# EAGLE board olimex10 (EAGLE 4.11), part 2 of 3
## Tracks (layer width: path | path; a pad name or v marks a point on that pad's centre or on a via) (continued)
DIO00  (via drill 0.61)  (3 unrouted) (continued)
  Bottom 0.254: v52.07,121.92 25.4,121.92 IC13.12 | v68.58,27.94 67.31,29.21 42.55,29.21 41.27,27.94 RS08.36 39.37,27.94 39.37,24.77 38.73,24.13 25.4,24.13 24.13,22.86 IC34.8 18.41,22.86 v15.88,20.32 | IC43.17 277.5,22.23 299.08,22.23 304.8,27.94 304.8,60.33 279.4,60.33 278.13,59.05 278.13,57.15 280.04,57.15 281.31,58.42 RF08A.36 | IC48.1 55.88,163.83 60.96,158.75 130.81,158.75 131.44,159.38 143.51,159.38 144.78,158.12 222.25,158.12 223.52,159.38 227.33,159.38 229.24,157.48 248.92,157.48 250.19,158.75 251.46,157.48 251.46,154.94 245.75,154.94 244.47,153.67 SV3.2
DIO01  (via drill 0.61)  (3 unrouted)
  Top 0.254: v75.56,16.51 75.56,18.41 74.93,19.05 75.56,19.68 75.56,23.5 IC35.14 | v24.77,13.34 24.77,26.04 IC34.6 | IC13.11 29.21,123.19 29.21,125.73 27.3,127.64 7.62,127.64 7.62,26.04 12.06,21.59 17.14,21.59 17.14,12.7 15.24,10.79 SV1.4 | RF08A.37 284.48,44.45 280.67,40.64 280.67,24.13 282.57,22.23 282.57,3.17 276.23,3.17 274.32,5.08 IC43.15 | IC45.15 276.23,69.22 283.21,69.22 283.21,120.02 284.48,121.28 RF08B.37 | v122.56,164.47 130.18,156.84 143.51,156.84 143.51,177.16 151.13,184.78 v151.13,189.23 | v247.65,191.13 247.65,155.57 246.38,154.31 SV3.4
  Bottom 0.254: IC13.11 27.3,121.28 51.44,121.28 IC14.11 | IC34.6 24.13,27.94 25.4,26.67 36.2,26.67 37.47,25.4 RS08.37 | v75.56,16.51 72.39,13.34 41.27,13.34 40.64,12.7 24.77,12.7 | 24.77,12.7 19.68,12.7 19.05,13.34 17.78,13.34 15.24,10.79 SV1.4 | 24.77,12.7 v24.77,13.34 | v122.56,164.47 121.92,163.83 111.12,163.83 107.95,167 69.85,167 69.85,163.83 69.22,163.19 62.87,163.19 IC48.3 | v151.13,189.23 151.76,189.87 191.13,189.87 191.77,189.23 194.31,191.77 211.46,191.77 212.09,191.13 v247.65,191.13
DIO02  (via drill 0.61)  (3 unrouted)
  Top 0.254: v76.83,30.48 v76.83,41.91 76.2,42.55 76.2,73.66 74.93,74.93 74.93,81.28 v71.75,84.45 | v36.2,41.91 35.56,41.27 v35.56,29.21 | v26.04,29.21 26.04,29.84 IC34.4 | SV1.6 v17.78,30.48 | v59.05,84.45 59.69,85.09 59.69,114.3 55.88,118.11 IC14.10 | RF08A.35 281.94,57.15 285.12,57.15 285.75,56.52 285.75,55.24 285.12,54.61 285.12,43.81 283.21,41.91 283.21,2.54 274.32,2.54 271.78,5.08 IC43.14 | v280.04,84.45 280.04,107.31 281.94,109.22 RF08B.35 | v248.92,161.29 SV3.6
  Bottom 0.254: IC13.10 31.11,116.2 46.35,116.2 46.99,116.84 54.61,116.84 55.88,118.11 IC14.10 | v36.2,41.91 v76.83,41.91 | v76.83,30.48 IC35.16 | RS08.35 36.83,27.94 v35.56,29.21 v26.04,29.21 | v17.78,30.48 20.32,33.02 IC34.4 | v71.75,84.45 v59.05,84.45 | v280.04,84.45 271.78,84.45 IC45.14 | v248.92,161.29 227.97,161.29 227.33,160.66 226.06,160.66 225.43,161.29 212.72,161.29 210.19,158.75 159.38,158.75 156.84,161.29 144.15,161.29 143.51,160.66 132.08,160.66 131.44,161.29 106.05,161.29 105.41,160.66 104.78,161.29 59.69,161.29 59.69,166.37 60.33,167 64.14,167 IC48.5
DIO03  (via drill 0.61)  (3 unrouted)
  Top 0.254: 25.4,35.56 26.04,34.92 v26.04,33.02 | IC34.2 25.4,35.56 | v68.58,31.75 72.39,35.56 IC35.18 | v19.68,38.1 20.32,37.47 SV1.8 | 25.4,35.56 25.4,64.77 26.67,66.04 26.67,114.3 30.48,118.11 IC13.9 | RF08A.33 279.4,55.24 281.31,53.34 281.31,42.55 280.04,41.27 280.04,18.41 281.31,17.14 281.31,12.06 279.4,10.16 279.4,4.45 276.23,4.45 275.59,5.08 275.59,7.62 274.95,8.26 271.14,8.26 IC43.13 | IC45.13 271.78,68.58 298.45,68.58 298.45,114.94 287.02,126.36 278.13,126.36 278.13,123.83 279.4,122.56 RF08B.33 | v250.19,157.48 251.46,156.21 SV3.8 | v131.44,158.12 IC50.1
  Bottom 0.254: IC13.9 33.02,116.84 45.72,116.84 46.35,117.47 53.98,117.47 54.61,118.11 54.61,121.28 56.52,121.28 IC14.9 | v26.04,33.02 27.3,31.75 33.02,31.75 34.29,30.48 RS08.33 38.73,30.48 40.01,31.75 v68.58,31.75 | v19.68,38.1 IC34.2 | v131.44,158.12 132.72,156.84 249.56,156.84 v250.19,157.48
DIO04  (via drill 0.61)  (3 unrouted)
  Top 0.254: SV1.10 22.86,9.53 24.13,8.26 24.13,6.99 25.4,5.71 39.37,5.71 39.37,19.68 41.91,22.23 v41.91,36.83 41.91,41.27 40.64,42.55 RS08.24 | v70.48,68.58 69.85,69.22 69.85,105.41 IC15.2 | v52.7,36.83 53.34,37.47 53.34,62.23 54.61,63.5 v54.61,67.31 | RF08A.24 266.06,58.42 265.43,57.78 265.43,53.98 266.7,52.7 IC42.21 | IC39.21 266.7,113.03 265.43,114.3 265.43,122.56 266.7,123.83 RF08B.24 | v219.71,171.45 219.71,174.62 212.09,182.25 212.09,196.22 170.18,196.22 165.74,191.77 147.32,191.77 138.43,182.88 138.43,179.71 133.99,179.71 133.35,180.34 133.35,183.51 128.91,183.51 128.27,182.88 128.27,167.64 129.54,166.37 IC50.3 | v253.37,172.72 254,172.09 SV3.10
  Bottom 0.254: IC26.17 31.75,66.04 32.38,66.67 33.66,66.67 34.29,67.31 v54.61,67.31 63.5,67.31 64.77,68.58 IC28.3 v70.48,68.58 | v41.91,36.83 v52.7,36.83 | v219.71,171.45 219.71,173.99 252.09,173.99 v253.37,172.72
DIO05  (via drill 0.61)  (3 unrouted)
  Top 0.254: v44.45,11.43 v44.45,40.64 v44.45,62.23 | v69.22,63.5 69.22,106.05 73.66,110.49 IC15.1 | RF08A.26 268.61,58.42 267.97,57.78 267.97,53.98 269.24,52.7 IC42.20 | IC39.20 269.24,113.03 267.97,114.3 267.97,122.56 269.24,123.83 RF08B.26 | v187.32,167 188.59,168.91 v188.59,170.81 | v250.19,168.28 250.19,173.35 250.82,173.99 254.63,173.99 254.63,156.21 256.54,154.31 SV3.12
  Bottom 0.254: v44.45,11.43 27.3,11.43 26.04,10.16 SV1.12 | v44.45,40.64 RS08.26 | IC26.15 31.75,60.96 33.02,62.23 v44.45,62.23 63.5,62.23 64.77,63.5 IC28.5 v69.22,63.5 | v187.32,167 136.53,167 IC50.5 | v188.59,170.81 189.23,170.18 205.1,170.18 205.74,170.81 210.82,170.81 213.36,168.28 214,168.28 214.63,167.64 249.56,167.64 v250.19,168.28
DIO06  (via drill 0.61)  (3 unrouted)
  Top 0.254: RS08.28 40.64,38.73 39.37,40.01 39.37,46.35 38.73,46.99 37.47,46.99 35.56,48.9 35.56,54.61 v34.29,55.88 34.29,57.78 v36.2,59.69 | v62.87,59.69 62.87,73.03 65.41,75.56 65.41,126.36 69.22,126.36 69.85,125.73 69.85,123.19 72.39,120.65 72.39,117.47 74.3,117.47 IC15.13 | v28.57,39.37 28.57,11.43 27.94,10.79 SV1.14 | RF08A.28 271.14,58.42 270.51,57.78 270.51,53.98 271.78,52.7 IC42.19 | IC39.19 271.78,113.03 270.51,114.3 270.51,122.56 271.78,123.83 RF08B.28 | v196.85,160.02 193.04,163.83 IC52.1 | v208.28,160.66 208.91,161.29 208.91,163.19 209.55,163.83 209.55,170.18 213.36,173.99 v213.36,179.71 | v253.37,179.71 257.18,175.9 257.18,161.93 258.44,160.66 258.44,153.67 SV3.14
  Bottom 0.254: v34.29,55.88 IC26.13 | v36.2,59.69 v62.87,59.69 63.5,59.69 64.77,58.42 IC28.7 | v28.57,39.37 38.73,39.37 40.01,38.1 RS08.28 | v196.85,160.02 197.49,159.38 207.01,159.38 v208.28,160.66 | v213.36,179.71 214,179.07 252.73,179.07 v253.37,179.71
DIO07  (via drill 0.61)  (3 unrouted)
  Top 0.254: v77.47,54.61 76.83,55.24 76.83,63.5 77.47,64.14 77.47,116.84 78.74,118.11 IC15.12 | SV1.16 30.48,10.79 31.75,12.06 31.75,16.51 32.38,17.14 32.38,41.27 31.11,42.55 31.11,50.16 IC26.11 | v45.72,52.07 v45.72,35.56 | RF08A.30 273.69,58.42 273.05,57.78 273.05,53.98 274.32,52.7 IC42.18 | IC39.18 274.32,113.03 273.05,114.3 273.05,122.56 274.32,123.83 RF08B.30 | v235.59,147.96 235.59,160.02 234.31,160.02 233.04,158.75 233.04,156.84 201.29,156.84 199.39,158.75 199.39,162.56 198.12,163.83 IC52.3
  Bottom 0.254: IC26.11 31.75,50.8 33.02,52.07 v45.72,52.07 57.78,52.07 59.05,53.34 IC28.9 68.58,53.34 69.85,54.61 v77.47,54.61 | v45.72,35.56 RS08.30 | v235.59,147.96 265.43,147.96 267.97,150.5 267.97,152.4 263.52,152.4 262.25,153.67 SV3.16
DIO08  (via drill 0.61)  (3 unrouted)
  Top 0.254: v43.18,54.61 v43.18,49.53 v43.18,33.02 43.18,22.23 41.91,20.95 41.91,15.24 v40.64,13.97 | v69.22,117.47 68.58,116.84 68.58,64.14 67.94,63.5 67.94,60.96 70.48,58.42 v70.48,52.07 | SV1.18 v33.02,13.97 | RF08A.32 276.23,58.42 275.59,57.78 275.59,53.98 276.86,52.7 IC42.17 | IC39.17 276.86,113.03 275.59,114.3 275.59,122.56 276.86,123.83 RF08B.32 | v212.09,163.83 214.63,166.37 v214.63,168.91 | v262.89,170.81 262.89,155.57 264.16,154.31 SV3.18
  Bottom 0.254: v43.18,54.61 29.21,54.61 27.94,55.88 IC26.8 | v43.18,33.02 RS08.32 | v43.18,49.53 48.26,49.53 48.9,48.9 49.53,48.9 50.8,50.16 57.15,50.16 59.05,52.07 v70.48,52.07 71.12,52.07 72.39,53.34 IC28.12 | v69.22,117.47 69.85,116.84 78.74,116.84 IC15.11 | v33.02,13.97 v40.64,13.97 | v212.09,163.83 210.19,163.83 209.55,163.19 203.2,163.19 IC52.5 | v214.63,168.91 215.26,168.28 248.92,168.28 251.46,170.81 v262.89,170.81
DIO09  (via drill 0.61)  (3 unrouted)
  Top 0.254: v27.3,33.02 27.3,29.21 26.67,28.57 26.67,6.35 36.2,6.35 36.83,6.99 36.83,8.26 35.56,9.53 SV1.20 | v78.11,59.69 78.11,62.23 82.55,66.67 82.55,116.84 83.82,118.11 IC15.10 | v18.41,36.83 17.14,38.1 v17.14,59.05 | RF08A.29 274.95,55.88 274.95,47.62 275.59,46.99 275.59,43.81 274.32,42.55 IC42.15 | IC39.15 274.32,97.79 275.59,99.06 275.59,113.03 274.32,114.3 RF08B.29 | v261.62,158.12 IC54.1
  Bottom 0.254: v27.3,33.02 28.57,34.29 32.38,34.29 | 32.38,34.29 35.56,34.29 36.83,35.56 RS08.29 | v78.11,59.69 76.83,58.42 IC28.14 71.12,58.42 69.85,57.15 37.47,57.15 34.92,59.69 29.21,59.69 28.57,60.33 24.77,60.33 24.13,60.96 IC26.6 19.05,60.96 v17.14,59.05 | 32.38,34.29 32.38,36.83 v18.41,36.83 | v261.62,158.12 266.06,153.67 SV3.20
DIO10  (via drill 0.61)  (3 unrouted)
  Top 0.254: v19.68,66.04 20.32,65.41 20.32,46.35 v19.68,45.72 | v35.56,45.72 36.83,44.45 36.83,42.55 37.47,41.91 36.83,41.27 36.83,40.01 | 36.83,40.01 38.1,38.73 RS08.27 | v67.31,45.09 71.75,49.53 71.75,61.59 IC28.16 | v85.09,84.45 85.09,116.84 86.36,118.11 IC15.9 | v80.64,83.19 78.11,80.64 v78.11,63.5 | 36.83,40.01 36.83,22.23 37.47,21.59 37.47,11.43 38.1,10.79 SV1.22 | RF08A.27 272.42,55.88 272.42,47.62 273.05,46.99 273.05,43.81 271.78,42.55 IC42.14 | IC39.14 271.78,97.79 273.05,99.06 273.05,113.03 271.78,114.3 RF08B.27 | v266.7,156.84 IC54.3
  Bottom 0.254: v19.68,45.72 v35.56,45.72 36.83,44.45 41.27,44.45 41.91,43.81 66.04,43.81 v67.31,45.09 | v19.68,66.04 IC26.4 | v85.09,84.45 83.82,83.19 v80.64,83.19 | IC28.16 v78.11,63.5 | v266.7,156.84 269.24,154.31 SV3.22
DIO11  (via drill 0.61)  (3 unrouted)
  Top 0.254: 33.02,64.77 33.02,52.07 34.29,50.8 v34.29,42.55 | 33.02,64.77 v33.02,67.94 | v70.48,66.04 70.48,66.67 72.39,68.58 IC28.18 70.48,71.75 70.48,89.53 72.39,91.44 v72.39,99.06 | 33.02,64.77 v33.66,64.77 | v90.17,99.69 90.17,116.84 88.9,118.11 IC15.8 | v46.99,38.1 46.99,6.35 42.55,6.35 41.91,6.99 41.91,8.26 40.64,9.53 SV1.24 | RF08A.25 269.88,55.88 269.88,47.62 270.51,46.99 270.51,43.81 269.24,42.55 IC42.13 | IC39.13 269.24,97.79 270.51,99.06 270.51,113.03 269.24,114.3 RF08B.25 | SV3.24 IC54.5
  Bottom 0.254: v33.02,67.94 32.38,67.31 27.94,67.31 24.13,71.12 IC26.2 | v34.29,42.55 36.2,40.64 RS08.25 38.73,40.64 40.01,39.37 45.72,39.37 v46.99,38.1 | v70.48,66.04 69.22,64.77 v33.66,64.77 | v90.17,99.69 89.53,99.06 v72.39,99.06
DIOEVEN  (via drill 0.61)  (2 unrouted)
  Top 0.254: v45.72,30.48 v45.72,26.67 | v60.33,114.94 62.23,113.03 62.23,92.08 60.33,90.17 60.33,40.64 61.59,39.37 61.59,23.5 64.77,20.32 IC35.9 | v287.02,88.9 285.75,90.17 285.75,125.09 285.12,125.73 279.4,125.73 RF08B.34
  Bottom 0.254: v45.72,26.67 59.69,26.67 IC35.9 | RS08.34 v45.72,30.48 | v60.33,114.94 59.69,114.3 46.99,114.3 46.35,114.94 24.77,114.94 IC13.13 | IC43.18 276.23,23.5 286.38,23.5 287.02,22.86 298.45,22.86 304.17,28.57 304.17,59.69 281.31,59.69 280.04,58.42 RF08A.34 | v287.02,88.9 276.86,88.9 IC45.18
DMA00  (via drill 0.61)  (3 unrouted)
  Top 0.254: v137.16,11.43 135.89,10.16 DMA0-3.7 128.91,4.45 v128.91,3.17 | 46.99,54.61 v45.72,53.34 | 46.99,54.61 v46.99,86.36 | SV2.1 v43.18,90.17 | v73.66,6.99 60.33,20.32 v60.33,39.37 | v47.62,39.37 46.99,40.01 46.99,54.61 | IC43.25 256.54,27.3 255.27,28.57 255.27,31.75 256.54,33.02 IC42.25 256.54,52.7 255.27,53.98 255.27,57.78 255.91,58.42 RF08A.16 | IC45.25 256.54,87.63 255.27,88.9 255.27,107.95 256.54,109.22 IC39.25 256.54,113.03 255.27,114.3 255.27,122.56 256.54,123.83 RF08B.16 | v121.28,189.87 121.28,191.13 71.75,191.13 IC47.9 | v191.77,190.5 v194.31,190.5 | v270.51,191.13 270.51,182.88 271.78,181.61 IC53.5 | v285.75,163.83 285.75,188.59 287.02,189.87 SV4.24
  Bottom 0.254: v137.16,11.43 162.56,11.43 163.83,12.7 IC38.8 | v45.72,53.34 RS08.16 | v46.99,86.36 SV2.1 | v43.18,90.17 35.56,90.17 33.66,88.27 19.05,88.27 19.05,85.72 18.41,85.09 17.14,85.09 15.88,83.82 SV2.24 | v128.91,3.17 128.27,2.54 96.52,2.54 93.98,5.08 78.11,5.08 77.47,4.45 76.2,4.45 v73.66,6.99 | v60.33,39.37 v47.62,39.37 | v121.28,189.87 123.83,187.32 135.25,187.32 135.89,187.96 135.89,191.13 166.37,191.13 167,190.5 v191.77,190.5 | v194.31,190.5 194.94,189.87 196.22,189.87 196.85,189.23 197.49,189.87 243.84,189.87 244.47,189.23 260.35,189.23 261.62,190.5 270.51,190.5 | 270.51,190.5 SV4.24 | 270.51,190.5 v270.51,191.13 | v285.75,163.83 287.65,163.83 288.93,162.56 SV4.1
DMA01  (via drill 0.61)  (3 unrouted)
  Top 0.254: 40.64,80.64 39.37,79.38 39.37,50.16 40.64,48.9 RS08.20 | 40.64,80.64 40.64,81.92 39.37,83.19 39.37,84.45 40.64,85.72 SV2.3 | v92.71,11.43 90.17,13.97 v90.17,44.45 | v57.78,79.38 v57.78,45.72 | 40.64,80.64 v41.91,79.38 | IC43.23 261.62,27.3 260.35,28.57 260.35,31.75 261.62,33.02 IC42.23 261.62,52.7 260.35,53.98 260.35,57.78 260.99,58.42 RF08A.20 | IC45.23 261.62,87.63 260.99,88.27 260.99,94.61 260.35,95.25 260.35,106.05 261.62,107.31 IC39.23 261.62,113.03 260.35,114.3 260.35,122.56 261.62,123.83 RF08B.20 | v80.01,186.06 65.41,186.06 IC47.11 | v138.43,184.15 146.05,191.77 146.05,193.68 149.22,196.85 280.67,196.85 280.67,173.99 281.94,172.72 280.67,171.45 280.67,166.37 285.75,161.29 288.29,161.29 288.29,163.19 289.56,164.47 SV4.3
  Bottom 0.254: IC38.6 163.83,17.78 162.56,16.51 139.7,16.51 135.89,12.7 DMA0-3.6 110.49,12.7 109.22,11.43 v92.71,11.43 | v90.17,44.45 69.22,44.45 67.31,46.35 58.42,46.35 v57.78,45.72 | v41.91,79.38 v57.78,79.38 | v80.01,186.06 87.63,178.44 136.53,178.44 138.43,180.34 v138.43,184.15
DMA02  (via drill 0.61)  (3 unrouted)
  Top 0.254: v49.53,55.88 v49.53,88.9 | v40.64,91.44 38.1,88.9 SV2.5 | v132.72,19.05 132.72,20.95 DMA0-3.2 | v84.45,20.32 80.64,24.13 v80.64,57.15 | IC43.26 254,27.3 252.73,28.57 252.73,31.75 254,33.02 IC42.26 254,52.7 252.73,53.98 252.73,57.78 253.37,58.42 RF08A.14 | IC45.26 254,87.63 252.73,88.9 252.73,109.22 254,110.49 IC39.26 254,113.03 252.73,114.3 252.73,122.56 254,123.83 RF08B.14 | v120.02,165.1 120.02,157.48 79.38,157.48 77.47,159.38 77.47,161.29 40.01,161.29 29.21,172.09 29.21,175.9 43.18,189.87 43.18,191.13 57.78,191.13 57.78,189.87 58.42,189.23 IC47.13
  Bottom 0.254: DMA0-3.2 135.89,22.86 137.16,21.59 162.56,21.59 163.83,22.86 IC38.4 | v49.53,88.9 46.99,91.44 v40.64,91.44 | RS08.14 v49.53,55.88 50.8,54.61 68.58,54.61 71.12,57.15 v80.64,57.15 | v132.72,19.05 132.08,18.41 94.61,18.41 92.71,20.32 v84.45,20.32 | v120.02,165.1 121.92,167 135.25,167 136.53,168.28 204.47,168.28 205.1,167.64 213.36,167.64 214,167 252.09,167 252.73,167.64 283.85,167.64 285.12,166.37 287.65,166.37 288.93,167.64 SV4.5
DMA03  (via drill 0.61)  (3 unrouted)
  Top 0.254: v139.06,29.21 139.06,24.77 DMA0-3.3 | v159.38,30.48 v161.93,27.94 | v48.26,85.09 v48.26,58.42 v48.26,48.26 | v93.34,21.59 90.81,24.13 90.81,43.81 91.44,44.45 91.44,45.72 v90.17,46.99 | IC43.27 251.46,27.3 250.19,28.57 250.19,31.75 251.46,33.02 IC42.27 251.46,52.7 250.19,53.98 250.19,57.78 250.82,58.42 RF08A.12 | IC45.27 251.46,87.63 250.82,88.27 250.82,94.61 250.19,95.25 250.19,98.42 251.46,99.69 IC39.27 251.46,113.03 250.19,114.3 250.19,122.56 251.46,123.83 RF08B.12 | v183.51,186.06 189.23,180.34 189.23,173.35 193.68,168.91 193.68,167 194.31,166.37 194.31,163.83 194.94,163.19 196.85,163.19 196.85,168.91 199.39,171.45 199.39,173.99 201.93,176.53 201.93,184.15 204.47,186.69 204.47,189.23 205.1,189.87 209.55,189.87 v209.55,175.26
  Bottom 0.254: v139.06,29.21 140.34,30.48 v159.38,30.48 | v161.93,27.94 IC38.2 | v48.26,85.09 37.47,85.09 36.2,86.36 SV2.7 | v48.26,58.42 RS08.12 | v93.34,21.59 95.89,19.05 125.09,19.05 126.36,20.32 DMA0-3.3 | v90.17,46.99 87.63,49.53 80.01,49.53 78.11,47.62 52.7,47.62 52.07,48.26 v48.26,48.26 | v183.51,186.06 140.34,186.06 IC49.9 | v209.55,175.26 210.19,175.9 280.67,175.9 281.31,175.26 285.12,175.26 286.38,176.53 287.65,176.53 288.29,175.9 288.29,170.81 289.56,170.81 SV4.7
DMA04  (via drill 0.61)  (3 unrouted)
  Top 0.254: v35.56,60.96 35.56,78.11 34.29,79.38 v34.29,82.55 | v124.46,80.01 124.46,73.03 125.73,71.75 v125.73,64.77 | v138.43,61.59 137.79,60.96 137.79,50.16 135.89,48.26 132.72,48.26 132.72,46.35 DMA4-7.7 | IC43.5 248.92,18.41 250.19,19.68 250.19,22.86 249.56,23.5 249.56,29.84 IC42.5 249.56,31.11 249.56,32.38 250.19,33.02 250.19,46.99 249.56,47.62 249.56,55.88 RF08A.9 | IC45.5 248.92,72.39 250.19,73.66 250.19,93.98 248.92,95.25 IC39.5 248.92,98.42 250.19,99.69 250.19,113.03 249.56,113.67 249.56,120.65 248.92,121.28 RF08B.9 | IC49.11 v139.06,196.22
  Bottom 0.254: v35.56,60.96 RS08.9 | SV2.9 33.02,85.72 34.29,85.72 v34.29,82.55 38.73,78.11 60.96,78.11 64.14,81.28 93.98,81.28 95.89,83.19 97.16,83.19 97.79,82.55 97.79,79.38 120.65,79.38 121.28,80.01 v124.46,80.01 | DMA4-7.7 135.89,44.45 139.7,48.26 153.03,48.26 155.57,45.72 160.66,45.72 161.93,46.99 IC31.8 | v125.73,64.77 135.25,64.77 v138.43,61.59 | v139.06,196.22 139.7,196.85 290.19,196.85 292.74,194.31 292.74,173.35 289.56,173.35 SV4.9
DMA05  (via drill 0.61)  (3 unrouted)
  Top 0.254: v35.56,79.38 v36.83,78.11 36.83,73.03 36.2,72.39 36.2,61.59 36.83,60.96 36.83,60.33 38.1,59.05 RS08.11 | v138.43,41.91 138.43,43.18 DMA4-7.6 | v158.12,40.01 160.02,41.91 160.02,50.8 v161.29,52.07 | v62.23,78.11 61.59,77.47 61.59,44.45 63.5,42.55 v63.5,40.64 | IC43.6 251.46,18.41 252.73,19.68 252.73,22.86 252.09,23.5 252.09,29.84 IC42.6 252.09,31.11 252.09,32.38 252.73,33.02 252.73,46.99 252.09,47.62 252.09,55.88 RF08A.11 | IC45.6 251.46,72.39 252.73,73.66 252.73,87.63 251.46,88.9 IC39.6 252.09,97.16 252.09,109.86 252.73,110.49 252.73,113.03 252.09,113.67 252.09,120.65 251.46,121.28 RF08B.11 | v128.27,194.31 128.27,191.77 127,190.5 IC49.13
  Bottom 0.254: v35.56,79.38 31.75,83.19 31.75,84.45 30.48,85.72 SV2.11 | v138.43,41.91 140.34,40.01 v158.12,40.01 | v161.29,52.07 IC31.6 | v36.83,78.11 37.47,77.47 61.59,77.47 v62.23,78.11 | v63.5,40.64 64.77,39.37 118.75,39.37 123.83,44.45 130.81,44.45 133.35,46.99 DMA4-7.6 | v128.27,194.31 128.91,194.94 171.45,194.94 172.72,196.22 289.56,196.22 292.1,193.68 292.1,175.9 289.56,175.9 SV4.11
DMA06  (via drill 0.61)  (3 unrouted)
  Top 0.254: v19.05,55.88 18.41,56.52 18.41,59.05 16.51,60.96 v16.51,75.56 16.51,80.64 13.97,83.19 13.97,91.44 v14.61,92.08 | v117.47,59.69 116.2,60.96 v116.2,77.47 | v90.81,78.11 91.44,78.74 91.44,93.98 90.17,95.25 90.17,98.42 88.9,99.69 v88.9,100.97 | IC43.7 254,18.41 255.27,19.68 255.27,22.86 254.63,23.5 254.63,29.84 IC42.7 254.63,31.11 254.63,32.38 255.27,33.02 255.27,46.99 254.63,47.62 254.63,55.88 RF08A.13 | IC45.7 254,72.39 255.27,73.66 255.27,87.63 254,88.9 IC39.7 254,107.95 255.27,109.22 255.27,113.03 254.63,113.67 254.63,120.65 254,121.28 RF08B.13 | v207.01,177.16 207.01,185.42 205.74,186.69 IC51.9
  Bottom 0.254: IC31.4 163.83,57.15 162.56,55.88 137.16,55.88 135.89,57.15 DMA4-7.2 133.35,57.15 132.72,57.78 129.54,57.78 127.64,59.69 v117.47,59.69 | v19.05,55.88 20.32,55.88 21.59,57.15 36.2,57.15 37.47,55.88 RS08.13 | v16.51,75.56 24.13,83.19 24.13,85.09 26.04,85.09 27.3,86.36 SV2.13 | v116.2,77.47 115.57,78.11 v90.81,78.11 | v88.9,100.97 88.27,100.33 73.66,100.33 73.03,100.97 61.59,100.97 60.96,101.6 45.09,101.6 41.91,98.42 12.06,98.42 11.43,97.79 11.43,95.89 10.79,95.89 8.26,93.34 8.26,88.27 10.79,88.27 v14.61,92.08 | v207.01,177.16 207.65,177.8 281.31,177.8 282.57,179.07 287.65,179.07 288.93,177.8 SV4.13
DMA07  (via drill 0.61)  (3 unrouted)
  Top 0.254: v137.16,64.14 137.16,57.15 DMA4-7.3 | v36.83,49.53 36.83,51.44 38.1,52.7 RS08.15 | v113.67,45.72 117.47,49.53 v117.47,57.15 | v52.07,46.99 v52.07,92.71 | v25.4,89.53 SV2.15 | IC43.8 256.54,18.41 257.81,19.68 257.81,22.86 257.18,23.5 257.18,29.84 IC42.8 257.18,31.11 257.18,32.38 257.81,33.02 257.81,46.99 257.18,47.62 257.18,55.88 RF08A.15 | IC45.8 256.54,72.39 257.81,73.66 257.81,87.63 256.54,88.9 IC39.8 256.54,98.42 257.81,99.69 257.81,113.03 257.18,113.67 257.18,120.65 256.54,121.28 RF08B.15 | IC51.11 v207.65,194.94
  Bottom 0.254: v137.16,64.14 138.43,65.41 163.19,65.41 163.83,66.04 173.99,66.04 174.62,65.41 174.62,63.5 167.64,63.5 166.37,62.23 IC31.2 | v36.83,49.53 41.91,49.53 44.45,46.99 v52.07,46.99 88.9,46.99 90.17,45.72 v113.67,45.72 | v117.47,57.15 130.81,57.15 133.35,54.61 DMA4-7.3 | v25.4,89.53 28.57,92.71 v52.07,92.71 | v207.65,194.94 208.28,195.58 288.93,195.58 291.46,193.04 291.46,180.97 289.56,180.97 SV4.15
DMA08  (via drill 0.61)  (3 unrouted)
  Top 0.254: v137.79,83.82 137.79,81.92 DMA8-11.7 | v159.38,85.09 160.66,83.82 v160.66,81.28 | v33.02,50.8 32.38,50.16 v32.38,42.55 | v10.16,41.91 8.89,43.18 v8.89,81.28 | v130.81,80.64 130.18,81.28 v130.18,93.98 | v99.06,93.98 97.79,95.25 v97.79,99.06 | IC43.9 259.08,18.41 260.35,19.68 260.35,22.86 259.71,23.5 259.71,29.84 IC42.9 259.71,31.11 259.71,32.38 260.35,33.02 260.35,46.99 259.71,47.62 259.71,55.88 RF08A.17 | IC45.9 259.08,72.39 260.35,73.66 260.35,93.98 259.08,95.25 IC39.9 259.08,106.05 260.35,107.31 260.35,113.03 259.71,113.67 259.71,120.65 259.08,121.28 RF08B.17 | IC51.13 v195.58,194.31 | v288.29,191.77 288.29,184.78 289.56,183.51 SV4.17
  Bottom 0.254: v137.79,83.82 139.06,85.09 v159.38,85.09 | v160.66,81.28 IC24.8 | v32.38,42.55 31.75,41.91 v10.16,41.91 | 9.53,81.92 10.16,82.55 20.95,82.55 21.59,83.19 21.59,86.36 SV2.17 | v8.89,81.28 9.53,81.92 | v33.02,50.8 RS08.17 | v130.81,80.64 131.44,80.64 133.35,78.74 DMA8-11.7 | v99.06,93.98 v130.18,93.98 | v97.79,99.06 94.61,102.23 88.9,102.23 87.63,100.97 74.3,100.97 73.66,101.6 62.23,101.6 61.59,102.23 44.45,102.23 41.27,99.06 9.53,99.06 5.08,94.61 5.08,81.92 9.53,81.92 | v195.58,194.31 196.22,193.68 210.82,193.68 212.09,194.94 283.21,194.94 286.38,191.77 v288.29,191.77
DMA09  (via drill 0.61)  (3 unrouted)
  Top 0.254: v136.53,85.09 136.53,83.19 DMA8-11.6 | v42.55,63.5 41.91,62.87 41.91,46.99 40.01,46.99 38.73,48.26 RS08.19 | v45.09,63.5 46.35,64.77 46.35,85.72 45.72,86.36 45.72,87 v46.35,87.63 | IC43.10 261.62,18.41 262.89,19.68 262.89,22.86 262.25,23.5 262.25,29.84 IC42.10 262.25,31.11 262.25,32.38 262.89,33.02 262.89,55.24 262.25,55.88 RF08A.19 | IC45.10 261.62,72.39 262.89,73.66 262.89,88.27 261.62,89.53 IC39.10 261.62,97.79 262.89,99.06 262.89,120.02 261.62,121.28 RF08B.19 | v278.13,184.15 IC53.9
  Bottom 0.254: IC24.6 162.56,86.36 161.29,87.63 139.06,87.63 v136.53,85.09 128.27,85.09 127,86.36 52.07,86.36 50.8,87.63 v46.35,87.63 20.95,87.63 20.32,87 SV2.19 | v42.55,63.5 v45.09,63.5 | v278.13,184.15 287.65,184.15 288.93,185.42 SV4.19
DMA10  (via drill 0.61)  (3 unrouted)
  Top 0.254: v6.35,46.99 v6.35,83.19 | v126.36,91.44 125.73,90.81 v125.73,84.45 | v50.8,81.92 v50.8,45.72 | 265.43,29.21 265.43,19.68 264.16,18.41 IC43.11 | 265.43,29.21 IC42.11 | 265.43,29.21 265.43,46.99 264.16,48.26 RF08A.21 | 265.43,93.98 265.43,73.66 264.16,72.39 IC45.11 | 265.43,93.98 264.16,95.25 IC39.11 | 265.43,93.98 265.43,113.03 264.8,113.67 264.8,120.65 264.16,121.28 RF08B.21
  Bottom 0.254: IC24.4 163.83,91.44 162.56,90.17 137.16,90.17 135.89,91.44 DMA8-11.2 v126.36,91.44 | 36.2,46.99 37.47,45.72 RS08.21 | 36.2,46.99 v6.35,46.99 | v6.35,83.19 8.26,85.09 15.88,85.09 17.14,86.36 SV2.21 | v125.73,84.45 100.97,84.45 100.33,83.82 99.06,83.82 97.16,85.72 54.61,85.72 v50.8,81.92 | v50.8,45.72 50.16,46.35 41.91,46.35 41.27,46.99 36.2,46.99 | IC53.11 271.14,186.06 281.31,186.06 281.94,186.69 287.65,186.69 288.93,187.96 SV4.21
DMA11  (via drill 0.61)  (3 unrouted)
  Top 0.254: v161.93,96.52 v161.93,99.06 | DMA8-11.3 137.16,91.44 v137.16,98.42 130.18,105.41 130.18,108.58 128.27,110.49 128.27,120.02 v125.09,123.19 | v27.94,44.45 27.3,45.09 27.3,50.16 27.94,50.8 v27.94,58.42 | v19.05,59.69 19.05,65.41 18.41,66.04 18.41,82.55 19.05,83.19 19.05,84.45 18.41,85.09 16.51,85.09 | 16.51,85.09 15.24,85.09 SV2.23 | v16.51,126.36 16.51,85.09 | IC43.12 266.7,19.05 267.97,20.32 267.97,22.86 266.7,24.13 IC42.12 266.7,42.55 267.97,43.81 267.97,46.99 267.33,47.62 267.33,55.88 RF08A.23 | 267.97,93.98 267.97,73.66 266.7,72.39 IC45.12 | 267.97,93.98 266.7,95.25 IC39.12 | 267.97,93.98 267.97,113.03 267.33,113.67 267.33,120.65 266.7,121.28 RF08B.23
  Bottom 0.254: v137.16,98.42 161.29,98.42 v161.93,99.06 | v161.93,96.52 IC24.2 | v27.94,44.45 29.84,44.45 30.48,43.81 36.83,43.81 37.47,43.18 RS08.23 | v27.94,58.42 26.67,59.69 v19.05,59.69 | v125.09,123.19 124.46,122.56 93.34,122.56 92.71,121.92 63.5,121.92 59.05,126.36 v16.51,126.36 | IC53.13 266.06,189.87 285.75,189.87 286.38,189.23 287.65,189.23 288.93,190.5 SV4.23
DMA-IN\  (via drill 0.61)
  Top 0.254: IC34.1 22.86,48.26 24.77,50.16 24.77,71.75 IC26.1 22.86,76.83 24.13,78.11 24.13,109.22 25.4,110.49 IC13.4 | v19.05,12.06 19.68,12.7 19.68,36.83 v18.41,38.1
  Bottom 0.254: IC26.19 29.21,71.12 28.57,71.75 26.04,71.75 24.13,73.66 IC26.1 | v19.05,12.06 41.27,12.06 41.91,12.7 76.83,12.7 77.47,13.34 87,13.34 IC41.12 | v18.41,38.1 20.95,40.64 IC34.1
DMA-OUT\  (via drill 0.61)
  Top 0.254: IC35.1 64.14,42.55 64.14,71.75 IC28.1 | 75.56,40.01 75.56,69.22 IC28.19 | 75.56,40.01 IC35.19 | v76.2,19.05 76.2,29.84 75.56,30.48 75.56,40.01 | v92.71,19.05 IC41.9
  Bottom 0.254: v76.2,19.05 v92.71,19.05 | IC28.1 67.31,73.66 69.85,71.12 IC28.19
DONE  (via drill 0.61)  (1 unrouted)
  Top 0.254: v152.4,26.67 152.4,22.86 IC55.2 | v177.8,26.67 178.44,26.04 178.44,8.26 184.15,2.54 194.31,2.54 194.31,113.03 198.12,116.84 IC11.9 | v57.15,6.99 v64.77,14.61 | v132.08,15.24 133.35,13.97 139.7,13.97 139.7,10.16 140.97,8.89 145.41,8.89 145.41,19.68 v146.05,20.32 | IC54.13 266.06,174.62 270.51,174.62 270.51,153.03 271.78,151.76 SV3.23
  Bottom 0.254: v152.4,26.67 v177.8,26.67 | v57.15,6.99 50.8,6.99 50.16,6.35 42.55,6.35 41.27,7.62 SV1.23 | v64.77,14.61 66.67,16.51 69.85,16.51 72.39,19.05 74.93,19.05 76.2,17.78 129.54,17.78 v132.08,15.24 | v146.05,20.32 IC55.2
DRV01\  (via drill 0.61)  (2 unrouted)
  Top 0.254: v52.7,24.13 52.7,2.54 87.63,2.54 88.9,3.81 86.36,6.35 IC41.4 | JP1.3 v288.29,53.98 | JP2.3 v288.29,123.19
  Bottom 0.254: v52.7,24.13 42.55,24.13 41.27,25.4 RS08.38 | v288.29,123.19 286.38,123.19 285.12,124.46 RF08B.38 | v288.29,53.98 288.29,57.15 285.12,57.15 284.48,57.78 RF08A.38
DRV23\  (via drill 0.61)  (2 unrouted)
  Top 0.254: v53.98,5.71 53.98,44.45 v54.61,45.09 | v93.98,2.54 IC41.7
  Bottom 0.254: v93.98,2.54 57.15,2.54 v53.98,5.71 | v54.61,45.09 53.98,44.45 42.55,44.45 41.27,45.72 RS08.22 | JP1.1 287.02,45.72 278.76,53.98 266.7,53.98 265.43,55.24 265.43,57.78 264.16,57.78 RF08A.22 | JP2.1 287.02,111.76 278.13,120.65 266.06,120.65 265.43,121.28 265.43,123.83 264.16,123.83 RF08B.22
DRVOK\  (via drill 0.61)  (2 unrouted)
  Top 0.254: IC21.13 80.64,103.5 79.38,103.5 IC21.14 78.74,102.87 80.01,101.6 v80.01,84.45 | v59.05,83.19 59.05,43.81 55.88,40.64 v55.88,22.86
  Bottom 0.254: 43.81,19.05 40.64,22.23 RS08.40 | 43.81,19.05 45.09,17.78 R2.1 | v80.01,84.45 78.74,83.19 v59.05,83.19 | v55.88,22.86 52.07,19.05 43.81,19.05 | RF08A.40 D4.A | RF08B.40 D8.A
DRVSELA\  (3 unrouted)
  Top 0.254: 264.16,44.45 263.52,43.81 263.52,32.38 262.89,31.75 262.89,24.13 264.16,22.86 IC43.22
  Bottom 0.254: 287.65,27.3 288.93,26.04 | 287.65,27.3 269.88,27.3 IC43.22 264.16,19.68 263.52,19.05 263.52,15.88 262.89,15.24 R3.1 | 301.62,57.78 301.62,27.3 287.65,27.3
DRVSELB\  (3 unrouted)
  Top 0.254: 264.16,110.49 263.52,109.86 263.52,98.42 262.89,97.79 262.89,89.53 264.16,88.27 IC45.22
  Bottom 0.254: 288.93,92.08 287.65,93.34 271.14,93.34 IC45.22 262.25,84.45 242.57,84.45 236.85,78.74 R4.1
EIE  (via drill 0.61)  (1 unrouted)
  Top 0.254: 199.39,8.89 v197.49,6.99 | 199.39,8.89 INTENB.6 200.66,5.71 207.01,5.71 208.28,6.99 208.28,25.4 IC37.2 | v5.08,100.33 5.08,8.89 13.34,8.89 14.61,7.62 SV1.3 | v74.93,94.61 v74.93,106.05 | v136.53,87.63 139.06,85.09 139.06,74.93 138.43,74.3 v138.43,71.75 | v196.22,69.85 196.85,69.22 196.85,46.99 195.58,45.72 195.58,22.86 199.39,19.05 199.39,8.89 | v198.12,177.8 199.39,179.07 v199.39,183.51 | v234.95,184.15 236.85,186.06 242.57,186.06 242.57,175.26 245.11,172.72 245.11,153.03 246.38,151.76 SV3.3 | v67.94,168.28 IC48.11
  Bottom 0.254: v197.49,6.99 187.32,6.99 185.42,8.89 160.02,8.89 158.75,10.16 IC55.9 | v5.08,100.33 10.79,106.05 v74.93,106.05 | v74.93,94.61 79.38,90.17 109.22,90.17 110.49,91.44 125.09,91.44 128.27,88.27 132.72,88.27 133.35,87.63 v136.53,87.63 | v138.43,71.75 139.06,71.12 177.8,71.12 178.44,71.75 180.34,71.75 182.25,69.85 v196.22,69.85 | v67.94,168.28 115.57,168.28 118.11,170.81 122.56,170.81 123.19,170.18 133.99,170.18 134.62,170.81 143.51,170.81 146.69,173.99 170.81,173.99 173.99,177.16 197.49,177.16 v198.12,177.8 | v199.39,183.51 200.03,182.88 210.19,182.88 211.46,184.15 v234.95,184.15
ERROR  (via drill 0.61)
  Top 0.254: v170.18,96.52 167.64,93.98 167.64,54.61 168.28,53.98 168.28,53.34 167.64,52.7 167.64,48.9 168.91,47.62 168.91,40.01 169.54,39.37 169.54,35.56 170.18,34.92 170.18,29.21 163.83,29.21 163.19,28.57 163.19,18.41 IC55.10 | v180.34,119.38 180.97,118.75 180.97,97.16 181.61,96.52 v181.61,94.61
  Bottom 0.254: v170.18,96.52 171.45,97.79 173.99,97.79 175.9,95.89 179.71,95.89 180.97,94.61 v181.61,94.61 211.46,94.61 212.72,95.89 212.72,98.42 211.46,98.42 IC12.6 | v180.34,119.38 IC7.2
EXAD0\  (via drill 0.61)
  Top 0.254: v12.06,88.27 11.43,87.63 11.43,74.3 13.97,71.75 13.97,65.41 12.7,64.14 C35L.34
  Bottom 0.254: v12.06,88.27 17.14,93.34 29.84,93.34 IC20.9
EXAD1\  (via drill 0.61)
  Top 0.254: v9.53,89.53 10.16,88.9 10.16,69.22 12.7,66.67 C35L.36
  Bottom 0.254: v9.53,89.53 13.97,93.98 25.4,93.98 IC20.7
EXAD2\  (via drill 0.61)
  Top 0.254: v10.79,94.61 10.79,71.12 12.7,69.22 C35L.38
  Bottom 0.254: v10.79,94.61 20.95,94.61 IC20.5
F.1  (via drill 0.61)  (1 unrouted)
  Top 0.254: SV2.6 38.1,84.45 36.83,85.72 36.83,101.6 35.56,102.87 IC20.11 v35.56,139.06 | IC30.8 208.91,45.09 208.91,81.92 FIELD.3 205.1,89.53 v205.1,130.18 | v152.4,175.9 152.4,176.53 v167.64,192.41 | v278.13,193.68 280.04,191.77 v280.04,172.72 | v70.48,175.9 IC47.5
  Bottom 0.254: v35.56,139.06 37.47,140.97 92.71,140.97 93.98,139.7 150.5,139.7 151.76,138.43 153.03,138.43 154.31,139.7 155.57,139.7 156.21,139.06 156.21,134.62 200.66,134.62 v205.1,130.18 | v70.48,175.9 123.83,175.9 124.46,176.53 127,176.53 127.64,175.9 v152.4,175.9 | v167.64,192.41 168.28,191.77 190.5,191.77 191.77,193.04 211.46,193.04 212.72,194.31 277.5,194.31 v278.13,193.68 | v280.04,172.72 285.12,167.64 SV4.6
F.2  (via drill 0.61)  (1 unrouted)
  Top 0.254: SV2.4 40.64,84.45 41.91,85.72 41.91,99.69 v38.73,102.87 43.18,107.31 v43.18,111.12 | v215.26,41.27 214.63,41.91 v214.63,86.36 v214.63,107.95 | v110.49,107.95 111.76,109.22 113.03,109.22 113.03,102.23 115.57,99.69 119.38,99.69 119.38,108.58 v118.75,109.22 | v151.13,177.16 v162.56,188.59 | v248.92,184.15 250.19,182.88 250.19,179.71 256.54,173.35 v256.54,161.29
  Bottom 0.254: v38.73,102.87 38.1,102.23 32.38,102.23 IC20.13 | v215.26,41.27 IC30.11 | v214.63,86.36 FIELD.2 | v43.18,111.12 44.45,112.39 44.45,113.67 68.58,113.67 72.39,109.86 99.69,109.86 100.97,108.58 107.95,108.58 109.22,107.31 109.86,107.31 v110.49,107.95 | v118.75,109.22 120.02,110.49 128.27,110.49 128.91,109.86 177.16,109.86 179.07,107.95 v214.63,107.95 | v151.13,177.16 60.96,177.16 IC47.3 | v162.56,188.59 163.19,189.23 186.69,189.23 191.13,184.78 196.85,184.78 197.49,185.42 234.95,185.42 236.85,183.51 242.57,183.51 243.21,184.15 v248.92,184.15 | v256.54,161.29 278.13,161.29 278.76,161.93 280.04,161.93 280.67,161.29 285.12,161.29 287.02,159.38 289.56,159.38 290.83,160.66 290.83,163.83 288.93,163.83 287.65,165.1 SV4.4
F.3  (via drill 0.61)  (1 unrouted)
  Top 0.254: v41.27,101.6 44.45,98.42 44.45,95.25 | 44.45,95.25 44.45,85.72 43.18,84.45 SV2.2 | v220.34,77.47 220.34,57.15 217.17,57.15 216.53,56.52 216.53,45.09 IC30.13 215.9,40.64 215.9,24.77 v212.72,21.59 | v43.81,95.25 44.45,95.25 | v71.75,89.53 76.2,85.09 v76.2,76.83 | v106.68,69.85 107.95,68.58 v107.95,28.57 | v62.23,191.13 62.23,186.69 IC47.1 | v281.94,192.41 284.48,189.87 284.48,163.83 285.75,162.56 SV4.2
  Bottom 0.254: v41.27,101.6 27.94,101.6 IC20.15 | v220.34,77.47 213.36,77.47 212.09,76.2 FIELD.6 | v43.81,95.25 44.45,94.61 66.67,94.61 v71.75,89.53 | v76.2,76.83 83.19,69.85 v106.68,69.85 | v107.95,28.57 111.12,25.4 122.56,25.4 123.83,24.13 168.91,24.13 171.45,21.59 v212.72,21.59 | v62.23,191.13 62.87,191.77 167,191.77 167.64,191.13 191.13,191.13 192.41,192.41 212.09,192.41 212.72,191.77 247.01,191.77 247.65,192.41 v281.94,192.41
GND  (3 unrouted)
  Top 0.254: IC14.2 IC14.13 | IC20.17 IC13.2 19.68,111.12 18.41,111.12 IC13.1 | IC20.10 35.56,97.79 34.29,99.06 34.29,109.22 33.02,110.49 IC13.7 | IC14.1 45.09,112.39 43.18,112.39 C14.2 | RS08.31 38.1,32.38 39.37,31.11 39.37,24.77 38.1,23.5 RS08.39 | C35L.1 C35L.3 C35L.5 C35L.7 C35L.9 C35L.11 C35L.13 C35L.15 C35L.17 C35L.19 C35L.21 C35L.23 C35L.25 C35L.27 C35L.29 C35L.31 C35L.33 C35L.35 C35L.37 C35L.39 15.24,80.64 12.7,83.19 SV2.26 SV2.25 13.34,86.36 13.34,93.34 11.43,95.25 11.43,95.89 10.16,97.16 C20.2 10.16,98.42 13.97,102.23 13.97,111.12 15.24,112.39 C13.2 | 150.5,62.23 150.5,75.56 DAR8-11.8 147.96,78.11 147.96,84.45 | 147.96,84.45 DAR8-11.4 | 147.96,84.45 147.96,96.52 C27.2 151.13,97.16 152.4,98.42 152.4,109.86 154.94,112.39 C18.2 | IC31.10 165.1,34.92 166.37,33.66 C38.2 | C40.2 151.13,40.64 DAR4-7.8 147.96,43.81 147.96,50.16 | 147.96,50.16 DAR4-7.4 | 150.5,62.23 147.96,62.23 147.96,50.16 | 150.5,62.23 C42.2 | D35L.39 D35L.37 D35L.35 D35L.33 D35L.31 D35L.29 D35L.27 D35L.25 D35L.23 D35L.21 D35L.19 D35L.17 D35L.15 D35L.13 D35L.11 D35L.9 D35L.7 D35L.5 D35L.3 D35L.1 | IC28.10 66.04,45.09 67.31,43.81 C35.2 67.31,42.55 67.94,41.91 67.94,32.38 67.31,31.75 71.75,27.3 | 71.75,26.04 71.75,24.77 IC35.13 | 71.75,26.04 IC35.15 | 71.75,27.3 71.75,26.04 | 71.75,27.3 71.75,31.11 IC35.17 | IC35.10 73.03,10.79 73.03,9.53 74.3,8.26 75.56,8.26 75.56,8.89 C41.2 | C39.2 135.89,74.93 DMA8-11.8 132.72,78.11 132.72,84.45 DMA8-11.4 | D36L.39 D36L.37 D36L.35 D36L.33 D36L.31 D36L.29 D36L.27 D36L.25 D36L.23 D36L.21 D36L.19 D36L.17 D36L.15 D36L.13 D36L.11 D36L.9 D36L.7 D36L.5 D36L.3 D36L.1
  Top 0.254: DMA0-3.4 131.44,17.78 131.44,22.23 133.35,24.13 136.53,24.13 136.53,27.94 C46.2 | C23.2 104.14,9.53 102.87,10.79 102.87,20.32 104.14,21.59 IC36.4 104.14,24.13 105.41,25.4 105.41,40.64 106.68,41.91 IC32.5 | J14.2 J13.2 J12.2 J11.2 J10.2 J9.2 J8.2 | D34L.1 D34L.3 D34L.5 D34L.7 D34L.9 D34L.11 D34L.13 D34L.15 D34L.17 D34L.19 D34L.21 D34L.23 D34L.25 D34L.27 D34L.29 D34L.31 D34L.33 D34L.35 D34L.37 D34L.39 | INTENB.4 196.22,9.53 197.49,9.53 INTENB.5 | 170.81,7.62 IC38.10 | 170.81,7.62 IC38.11 | 170.81,10.79 170.81,7.62 | IC38.13 170.81,10.79 | 170.81,10.79 170.81,15.88 | 170.81,15.88 IC38.15 | 170.81,15.88 170.81,20.95 IC38.17 | INTENB.8 INTENB.9 205.74,19.05 203.2,21.59 C36L.1 C36L.3 C36L.5 C36L.7 C36L.9 C36L.11 C36L.13 C36L.15 C36L.17 C36L.19 C36L.21 C36L.23 C36L.25 C36L.27 C36L.29 C36L.31 C36L.33 C36L.35 C36L.37 C36L.39 | IC37.10 208.91,9.53 208.91,15.88 IC37.6 | FIELD.8 211.46,70.48 211.46,64.77 212.09,64.14 C30.2 212.72,63.5 212.72,76.83 FIELD.5 210.19,79.38 210.19,80.64 FIELD.4 212.72,83.19 212.72,91.44 C44.2 212.09,95.25 IC12.7 212.72,98.42 212.72,114.3 C12.2 | C47.2 212.09,133.99 211.46,133.35 211.46,132.72 IC8.1 | C31.2 166.37,67.94 165.74,68.58 165.74,75.56 IC24.10 167,78.11 167,99.69 166.37,100.33 C24.2 167,101.6 172.72,107.31 IC18.7 | IC7.8 200.66,123.19 199.39,121.92 199.39,114.3 200.66,113.03 IC11.7 | 132.08,121.92 IC9.2 132.08,125.73 134.62,128.27 IC9.12 | 132.08,121.92 IC17.15 132.08,118.11 129.54,115.57 IC17.1 | IC1.7 28.57,136.53 29.84,136.53 IC1.8 | C45.- 183.51,138.43 183.51,135.25 185.42,133.35 IC7.15 185.42,128.27 182.88,125.73 IC7.1
  Top 0.254: IC10.12 162.56,128.27 160.02,125.73 IC10.2 | IC4.7 112.39,136.53 113.67,136.53 IC4.8 | IC5.7 144.78,134.62 143.51,133.35 143.51,127 144.78,125.73 IC9.7 144.15,123.83 144.15,121.92 132.08,121.92 | 312.42,25.4 G2.- | 312.42,25.4 G1.- 311.79,45.09 311.79,51.44 292.1,51.44 287.65,55.88 RF08A.39 | RF08A.31 277.5,55.88 277.5,48.26 278.13,47.62 278.13,44.45 277.5,43.81 277.5,41.91 276.23,40.64 276.23,31.11 IC42.16 276.86,29.21 275.59,27.94 275.59,8.89 276.86,7.62 IC43.16 | 312.42,25.4 IC44.7 | G3.- 313.06,109.86 314.32,109.86 G3.-@1 | G4.- 313.06,79.38 314.32,79.38 G4.-@1 | RF08B.31 276.86,121.28 278.13,120.02 278.13,110.49 276.86,109.22 IC39.16 | IC48.7 71.12,166.37 72.39,167.64 72.39,177.8 71.12,179.07 IC47.7 | IC50.7 139.7,166.37 140.97,167.64 140.97,179.07 139.7,180.34 IC49.7 | IC52.7 208.28,166.37 207.01,167.64 207.01,175.9 208.28,177.16 IC51.7 | SV4.26 SV4.25 289.56,192.41 291.46,190.5 291.46,161.29 289.56,159.38 276.86,159.38 IC54.7 276.86,166.37 278.13,167.64 278.13,177.8 276.86,179.07 IC53.7
  Bottom 0.254: IC14.1 46.35,111.12 47.62,111.12 IC14.2 50.16,109.86 51.44,109.86 | 51.44,109.86 IC14.4 | 51.44,109.86 59.05,109.86 IC14.7 | C13.2 15.88,113.03 16.51,112.39 17.14,112.39 IC13.1 | IC20.10 36.83,97.79 C33.2 43.18,98.42 61.59,98.42 IC33.8 64.77,97.79 C21.2 72.39,97.79 73.03,98.42 89.53,98.42 IC21.8 92.71,97.79 C22.2 99.06,98.42 114.94,98.42 IC22.7 C8.2 136.53,96.52 137.79,97.79 149.22,97.79 150.5,96.52 C27.2 | C14.2 34.29,113.03 IC13.7 31.11,109.86 22.23,109.86 IC13.2 | RS08.39 37.47,22.86 33.66,19.05 29.21,19.05 28.57,18.41 24.77,18.41 24.13,17.78 IC34.10 21.59,17.78 20.95,18.41 15.24,18.41 11.43,22.23 11.43,24.13 13.34,24.13 14.61,25.4 C35L.3 | C35L.17 C34.2 | C26.2 19.68,76.2 15.24,71.75 C35L.39 | C35L.23 IC26.10 | J2.2 10.79,50.8 12.06,52.07 13.34,52.07 14.61,53.34 C35L.25 | IC31.10 160.66,41.91 159.38,43.18 152.4,43.18 151.13,41.91 DAR4-7.8 148.59,41.91 147.32,43.18 132.08,43.18 | D35L.31 92.08,60.96 93.34,59.69 C29.2 93.98,60.33 104.78,60.33 IC29.5 108.58,56.52 112.39,56.52 IC29.8 | C28.2 67.94,76.2 69.85,78.11 78.74,78.11 85.72,71.12 D35L.39 89.53,71.12 93.34,74.93 C25.2 93.98,75.56 104.78,75.56 | 104.78,75.56 IC25.5 | 104.78,75.56 112.39,75.56 IC25.8 | C36.2 93.34,24.13 92.08,25.4 D35L.3 | D35L.17 92.08,43.18 93.34,44.45 C32.2 93.98,45.09 104.78,45.09 | IC32.5 104.78,45.09 | 104.78,45.09 112.39,45.09 IC32.8 | IC35.17 74.93,33.02 76.2,31.75 84.45,31.75 85.72,30.48 D35L.7 | IC55.7 148.59,7.62 147.32,8.89 137.16,8.89 135.89,7.62 DMA0-3.8 IC23.7 120.02,5.71 111.12,5.71 IC23.2 107.31,9.53 104.14,9.53 C23.2 97.79,8.89 IC41.8 94.61,9.53 76.2,9.53 C41.2
  Bottom 0.254: C39.2 135.25,62.23 133.99,63.5 D36L.33 | 132.08,43.18 133.35,41.91 DMA4-7.8 | 132.08,43.18 D36L.17 | DMA4-7.4 133.35,52.07 129.54,48.26 D36L.21 | IC36.4 104.78,22.23 106.05,22.23 IC36.5 108.58,24.77 112.39,24.77 IC36.8 115.57,21.59 125.09,21.59 126.36,22.86 D36L.1 | D36L.5 C46.2 | D34L.17 J6.2 | D34L.13 J8.2 | IC38.13 173.35,12.06 184.15,12.06 184.78,11.43 C43.2 185.42,12.06 193.68,12.06 INTENB.4 | IC19.7 203.2,91.44 C44.2 | C19.2 191.13,99.06 191.77,98.42 207.65,98.42 209.55,96.52 IC12.7 | INTENB.9 IC37.6 | C37.2 C36L.9 202.56,33.02 201.29,31.75 194.94,31.75 193.68,33.02 J10.2 | C36L.13 IC30.10 | FIELD.9 FIELD.8 C36L.39 | C36L.21 IC30.6 | INTENB.5 200.03,12.06 203.84,12.06 INTENB.8 | IC7.8 208.28,132.08 IC8.1 | C12.2 203.2,114.3 IC11.7 198.75,113.67 182.88,113.67 C11.2 182.25,113.03 181.61,112.39 173.35,112.39 IC18.7 170.81,113.67 154.94,113.67 C18.2 148.59,113.03 IC17.8 145.41,113.67 127,113.67 C17.2 | IC16.15 104.14,116.84 129.54,116.84 IC17.15 | C9.2 127.64,125.73 128.27,126.36 130.18,126.36 IC9.2 | C15.2 71.12,113.67 79.38,113.67 IC15.4 83.19,113.67 87,113.67 IC15.7 90.17,113.03 C16.2 97.79,113.03 IC16.1 100.97,109.86 114.94,109.86 IC16.8 118.11,113.03 C17.2 | IC17.1 128.27,113.03 C17.2 | C1.2 10.79,138.43 11.43,139.06 26.04,139.06 IC1.7 | IC1.8 31.11,137.79 36.83,137.79 37.47,138.43 C2.2 38.1,139.06 53.98,139.06 IC2.7 56.52,136.53 57.78,136.53 IC2.8 59.05,137.79 64.77,137.79 65.41,138.43 C3.2 66.04,139.06 81.92,139.06 IC3.7 84.45,136.53 85.72,136.53 IC3.8 87,137.79 92.71,137.79 93.34,138.43 C4.2 94.61,138.43 95.25,139.06 109.86,139.06 IC4.7 | IC7.1 181.61,125.73 C7.2 173.99,125.73 IC10.7 170.81,126.36 158.12,126.36
  Bottom 0.254: IC6.8 177.16,139.06 181.61,139.06 C45.- | IC9.7 146.05,125.73 C10.2 154.94,126.36 158.12,126.36 | 158.12,126.36 IC10.2 | C6.2 154.94,137.79 145.41,137.79 IC5.7 142.88,139.06 127,139.06 C5.2 126.36,138.43 125.73,137.79 114.94,137.79 IC4.8 | G2.- G2.-@1 | G1.- G1.-@1 | RF08A.31 277.5,55.88 278.76,54.61 285.12,54.61 286.38,55.88 RF08A.39 | RF08B.31 277.5,121.92 278.76,123.19 285.12,123.19 286.38,121.92 RF08B.39 | IC45.16 IC46.7 | 295.27,93.34 294.64,93.98 279.4,93.98 IC39.16 | IC46.7 295.27,93.34 | G4.- 301.62,90.81 297.81,90.81 IC46.7 | 295.27,93.34 G3.- | IC48.7 73.03,163.19 137.79,163.19 IC50.7 140.97,166.37 186.69,166.37 187.32,165.74 191.13,165.74 192.41,167 206.38,167 IC52.7 215.26,165.1 217.17,163.19 274.95,163.19 IC54.7
INT_RQ\  (via drill 0.61)
  Top 0.254: IC55.3 147.96,15.88 147.96,12.06 IC55.6 | v154.31,58.42 154.94,57.78 154.94,50.16 155.57,49.53 155.57,33.02 154.31,31.75 154.31,10.79 IC55.8
  Bottom 0.254: IC55.6 151.13,10.16 153.67,7.62 IC55.8 | v154.31,58.42 158.75,58.42 160.02,59.69 160.66,59.69 161.93,58.42 D34L.30
IOS\  (via drill 0.61)
  Top 0.254: v119.38,97.79 119.38,98.42 115.57,98.42 112.39,101.6 112.39,102.23 111.76,102.87 IC22.10 | v139.06,99.69 142.88,103.5 v142.88,106.05 | v153.67,107.31 154.94,106.05 v154.94,95.25 | v182.25,90.17 182.25,87.63 181.61,87 181.61,57.78 182.88,56.52 D34L.28
  Bottom 0.254: v119.38,97.79 135.25,97.79 137.16,99.69 v139.06,99.69 | v142.88,106.05 144.15,107.31 v153.67,107.31 | v154.94,95.25 177.16,95.25 v182.25,90.17
MEMSUPPLY  (via drill 0.61)  (1 unrouted)
  Top 0.508: v236.22,21.59 R3.2 D1.C | D3.C 278.76,13.34 278.76,42.55 D2.C | R4.2 D6.C | D7.C 278.76,79.38 278.76,108.58 D5.C
  Bottom 0.508: D1.C IC42.32 238.76,44.45 240.03,43.18 D2.C 280.04,42.55 281.94,42.55 IC44.14 | v236.22,21.59 IC43.32 | D6.C 236.85,111.12 238.12,111.12 IC39.32 241.3,109.22 D5.C 280.04,108.58 281.94,108.58 IC46.14 | R4.2 236.22,88.27 237.49,87 238.12,87 IC45.32
MYDEV\  (via drill 0.61)
  Top 0.254: 102.87,55.88 102.87,45.72 104.14,44.45 IC32.4 v104.14,38.1 | 102.87,55.88 104.14,57.15 IC29.4 | 102.87,55.88 102.87,71.12 104.14,72.39 IC25.4
  Bottom 0.254: v104.14,38.1 111.12,38.1 113.67,35.56 PAD1.1
N$1
  Top 0.254: IC36.9 PAD8.1
N$2  (via drill 0.61)
  Top 0.254: v194.31,130.18 194.31,121.92 193.04,120.65 IC11.11
  Bottom 0.254: v194.31,130.18 184.78,130.18 184.15,130.81 182.88,129.54 175.26,129.54 IC10.8
N$3  (via drill 0.61)
  Top 0.254: v145.41,49.53 144.78,48.9 144.78,11.43 140.97,11.43 140.34,12.06 140.34,15.24 DMA0-3.5
  Bottom 0.254: v145.41,49.53 DMA4-7.12
N$4  (via drill 0.61)
  Top 0.254: SW1.1 13.34,123.83 14.61,123.83 SW1.2 | SW1.3 18.41,123.83 19.68,123.83 SW1.4 20.95,123.83 22.23,123.83 SW1.5 23.5,123.83 24.77,123.83 SW1.6 26.04,123.83 27.3,123.83 SW1.7 | v40.64,93.98 37.47,97.16 v37.47,123.19 | v53.34,93.34 IC33.4
  Bottom 0.254: SW1.3 17.14,123.83 15.88,123.83 SW1.2 | SW1.7 28.57,123.83 29.84,123.83 SW1.8 31.11,123.83 36.83,123.83 v37.47,123.19 | v53.34,93.34 52.7,93.98 v40.64,93.98
N$5
  Top 0.254: IC36.15 PAD2.1
N$6
  Top 0.254: IC36.14 PAD3.1
N$7
  Top 0.254: IC36.13 PAD4.1
N$8
  Top 0.254: IC36.12 PAD5.1
N$9
  Top 0.254: IC36.11 PAD6.1
N$10
  Top 0.254: IC36.10 PAD7.1
N$11
  Top 0.254: IC36.7 111.76,24.13 116.84,29.21 PAD9.1
N$12
  Top 0.254: DAR4-7.14 155.57,56.52 155.57,60.33 156.21,60.96 157.48,60.96 157.48,73.66 155.57,75.56 155.57,87 DAR8-11.14 159.38,90.81 159.38,97.79 161.29,99.69 161.29,113.67 167,113.67 IC18.8
N$13  (via drill 0.61)
  Top 0.254: v145.41,50.8 144.78,51.44 144.78,81.28 DMA8-11.12
  Bottom 0.254: v145.41,50.8 137.16,50.8 135.89,49.53 DMA4-7.5
N$14  (via drill 0.61)
  Top 0.254: IC13.8 33.02,120.65 34.29,121.92 34.29,141.6 42.55,149.86 54.61,149.86 54.61,143.51 60.96,137.16 IC14.8 | v87.63,117.47 87.63,114.3 86.36,113.03 IC15.6
  Bottom 0.254: v87.63,117.47 87.63,121.28 62.87,121.28 IC14.8
N$15  (via drill 0.61)
  Top 0.254: v49.53,147.96 49.53,139.7 50.8,138.43 IC2.5 | v125.09,149.22 128.27,146.05 128.27,142.24 132.08,138.43 IC5.2
  Bottom 0.254: v49.53,147.96 51.44,149.86 124.46,149.86 v125.09,149.22
N$16  (via drill 0.61)
  Top 0.254: v146.69,15.24 147.32,15.88 v147.32,72.39 | v151.76,74.93 151.76,81.92 DAR8-11.5
  Bottom 0.254: v147.32,72.39 149.86,74.93 v151.76,74.93 | DMA0-3.12 v146.69,15.24
N$17
  Top 0.254: SW2.1 41.27,123.83 42.55,123.83 SW2.2 43.81,123.83 45.09,123.83 SW2.3 46.35,123.83 47.62,123.83 SW2.4 48.9,123.83 50.16,123.83 SW2.5 51.44,123.83 52.7,123.83 SW2.6 | IC33.5 55.88,97.79 54.61,99.06 54.61,121.92 53.34,123.19 SW2.6 | SW2.6 53.98,123.83 55.24,123.83 SW2.7 56.52,123.83 57.78,123.83 SW2.8
N$18
  Top 0.254: IC44.6 294,24.77 292.74,24.77 IC44.5
  Bottom 0.254: IC44.5 292.1,24.13 291.46,23.5 287.65,23.5 287.02,24.13 IC44.3
N$19  (via drill 0.61)
  Top 0.254: v67.31,99.06 67.94,99.69 67.94,123.83 SW3.1 | IC33.6 v58.42,99.69 | SW3.2 71.75,123.83 73.03,123.83 SW3.3 74.3,123.83 75.56,123.83 SW3.4 76.83,123.83 78.11,123.83 SW3.5 79.38,123.83 80.64,123.83 SW3.6 81.92,123.83 83.19,123.83 SW3.7 84.45,123.83 85.72,123.83 SW3.8
  Bottom 0.254: v58.42,99.69 59.05,99.06 v67.31,99.06 | SW3.2 70.48,123.83 69.22,123.83 SW3.1
N$20  (via drill 0.61)
  Top 0.254: v92.71,100.97 v92.71,123.19 | IC33.7 v60.96,100.33 | SW4.1 97.16,123.83 98.42,123.83 SW4.2 99.69,123.83 100.97,123.83 SW4.3 102.23,123.83 103.5,123.83 SW4.4 104.78,123.83 106.05,123.83 SW4.5 | SW4.6 109.86,123.83 111.12,123.83 SW4.7 112.39,123.83 113.67,123.83 SW4.8
  Bottom 0.254: v60.96,100.33 72.39,100.33 73.03,99.69 88.9,99.69 90.17,100.97 v92.71,100.97 | v92.71,123.19 93.34,123.83 95.89,123.83 SW4.1 | SW4.6 108.58,123.83 107.31,123.83 SW4.5
N$21  (via drill 0.61)
  Top 0.254: v77.47,147.96 77.47,143.51 78.11,142.88 78.11,139.06 78.74,138.43 IC3.5 | v127.64,147.96 135.89,147.96 135.89,139.7 137.16,138.43 IC5.4
  Bottom 0.254: v77.47,147.96 98.42,147.96 99.69,149.22 123.83,149.22 125.09,147.96 v127.64,147.96
N$22  (via drill 0.61)
  Top 0.254: 140.34,52.7 140.34,41.27 142.24,39.37 142.24,26.67 140.97,26.67 140.34,26.04 140.34,22.23 DMA0-3.14 | 140.34,52.7 DMA4-7.14 | 140.34,52.7 140.34,60.96 141.6,60.96 142.24,61.59 142.24,73.03 140.34,74.93 140.34,87 DMA8-11.14 144.15,90.81 v144.15,106.05 | v170.18,106.05 IC18.6
  Bottom 0.254: v170.18,106.05 v144.15,106.05
N$23
  Bottom 0.254: IC1.5 24.77,135.25 115.57,135.25 116.84,136.53 128.91,136.53 IC5.1
N$24
  Top 0.254: IC4.5 106.68,138.43 106.05,139.06 106.05,142.88 105.41,143.51 105.41,146.05 109.86,150.5 138.43,150.5 138.43,139.7 139.7,138.43 IC5.5
N$25  (via drill 0.61)
  Top 0.254: v154.31,49.53 153.67,50.16 153.67,57.78 153.03,58.42 153.03,75.56 152.4,76.2 v152.4,83.82
  Bottom 0.254: DAR4-7.5 v154.31,49.53 | v152.4,83.82 DAR8-11.12
N$26
  Top 0.254: IC22.1 101.6,97.79 102.87,99.06 102.87,113.03 107.31,117.47 111.12,117.47 111.12,118.75 IC16.11
N$27  (via drill 0.61)
  Top 0.254: v133.35,106.05 137.16,109.86 IC17.4
  Bottom 0.254: v133.35,106.05 111.12,106.05 IC22.11
N$28  (via drill 0.61)
  Top 0.254: v184.15,121.28 184.15,91.44 185.42,90.17 IC19.1
  Bottom 0.254: v184.15,121.28 185.42,122.56 191.13,122.56 IC7.5
N$29
  Top 0.254: RA.2 RB.1 220.98,122.56 222.25,123.83 222.25,125.73 IC8.7
N$30
  Top 0.254: IC12.2 210.19,109.86 210.19,111.12 IC12.1 210.82,117.47 212.72,119.38 212.72,125.09 IC8.3 209.55,127 208.28,128.27 RL.2
N$31
  Top 0.254: IC18.11 165.1,120.65 166.37,121.92 166.37,129.54 167.64,130.81 IC10.10
N$32
  Top 0.254: C47.1 217.17,133.99 216.53,133.35 216.53,128.91 IC8.6
  Bottom 0.254: 215.26,125.73 216.53,127 IC8.6 | 215.26,125.73 211.46,121.92 RB.2 | 215.26,125.73 214.63,125.73 IC8.2
N$33
  Top 0.254: IC19.11 193.04,97.79 191.77,99.06 191.77,129.54 193.04,130.81 IC7.12
N$34
  Top 0.254: IC8.5 C48.2
N$35
  Top 0.254: JP1.2 285.75,45.72 285.75,27.94 284.48,26.67 IC44.2
  Bottom 0.254: IC44.2 283.85,24.77 282.57,24.77 IC44.1
N$36
  Top 0.254: G4.+@1 D7.A | G4.+@2 294,75.56 292.74,75.56 G4.+@1 | G4.+@3 294,84.45 292.74,84.45 G4.+ 293.37,82.55 293.37,81.28 G4.+@4 293.37,78.74 293.37,77.47 G4.+@1
N$37
  Top 0.254: IC12.9 217.81,99.69 217.81,100.97 IC12.10 217.81,102.23 217.81,103.5 IC12.11
N$38
  Top 0.254: IC46.6 294,90.81 292.74,90.81 IC46.5
  Bottom 0.254: IC46.3 288.93,89.53 290.19,89.53 IC46.5
N$39
  Top 0.254: JP2.2 286.38,112.39 286.38,102.23 288.29,100.33 288.29,88.9 287.02,87.63 284.48,87.63 IC46.2
  Bottom 0.254: IC46.1 282.57,90.81 283.85,90.81 IC46.2
N$40
  Bottom 0.254: IC12.5 212.09,101.6 217.17,96.52 IC12.8
N$41
  Top 0.254: G3.+@1 D5.A | G3.+@2 294,106.05 292.74,106.05 G3.+@1 | G3.+@3 294,114.94 292.74,114.94 G3.+ 293.37,113.03 293.37,111.76 G3.+@4 293.37,109.22 293.37,107.95 G3.+@1
N$42
  Top 0.254: R5.1 10.16,183.51 12.7,186.06 F.3.A
N$43
  Top 0.254: R6.1 25.4,183.51 27.94,186.06 F.2.A
N$44
  Top 0.254: R7.1 40.64,183.51 43.18,186.06 F.1.A
N$45
  Top 0.254: R8.1 78.74,183.51 81.28,186.06 DEA8.A
N$46
  Top 0.254: R9.1 93.98,183.51 96.52,186.06 DEA7.A
N$47
  Top 0.254: R10.1 109.22,183.51 111.76,186.06 DEA6.A
N$48
  Top 0.254: R11.1 147.32,183.51 149.86,186.06 DEA5.A
N$49
  Top 0.254: R12.1 162.56,183.51 165.1,186.06 DEA4.A
N$50
  Top 0.254: R13.1 177.8,183.51 180.34,186.06 DEA3.A
N$51
  Top 0.254: R14.1 215.9,183.51 218.44,186.06 DEA2.A
N$52
  Top 0.254: R15.1 231.14,183.51 233.68,186.06 DEA1.A
N$53
  Top 0.254: SW1.16 14.61,130.18 19.05,130.18 19.05,133.99 20.32,135.25 IC1.4
N$54
  Top 0.254: SW1.15 15.24,133.35 17.78,135.89 IC1.3
N$55
  Bottom 0.254: SW1.14 17.78,133.35 15.24,135.89 IC1.2
N$56
  Bottom 0.254: IC1.1 16.51,133.35 16.51,130.18 18.41,130.18 SW1.13
N$57  (via drill 0.61)
  Top 0.254: v19.05,135.25 19.05,140.97 17.78,142.24 IC1.14
  Bottom 0.254: v19.05,135.25 22.23,135.25 SW1.11
N$58
  Top 0.254: SW1.10 24.13,135.89 24.13,139.7 20.32,143.51 IC1.13
N$59
  Top 0.254: SW1.9 26.67,135.89 26.67,139.7 22.86,143.51 IC1.12
N$60
  Top 0.254: SW1.12 22.86,133.35 21.59,134.62 21.59,139.7 19.05,142.24 19.05,146.05 18.41,146.69 15.24,146.69 IC1.15
N$61
  Top 0.254: SW2.16 40.64,133.35 41.91,134.62 41.91,138.43 42.55,139.06 47.62,139.06 47.62,137.79 IC2.4
N$62
  Top 0.254: SW2.15 43.18,133.35 45.72,135.89 IC2.3
N$63
  Top 0.254: SW2.14 43.81,130.18 41.91,130.18 41.91,133.35 43.18,134.62 IC2.2
N$64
